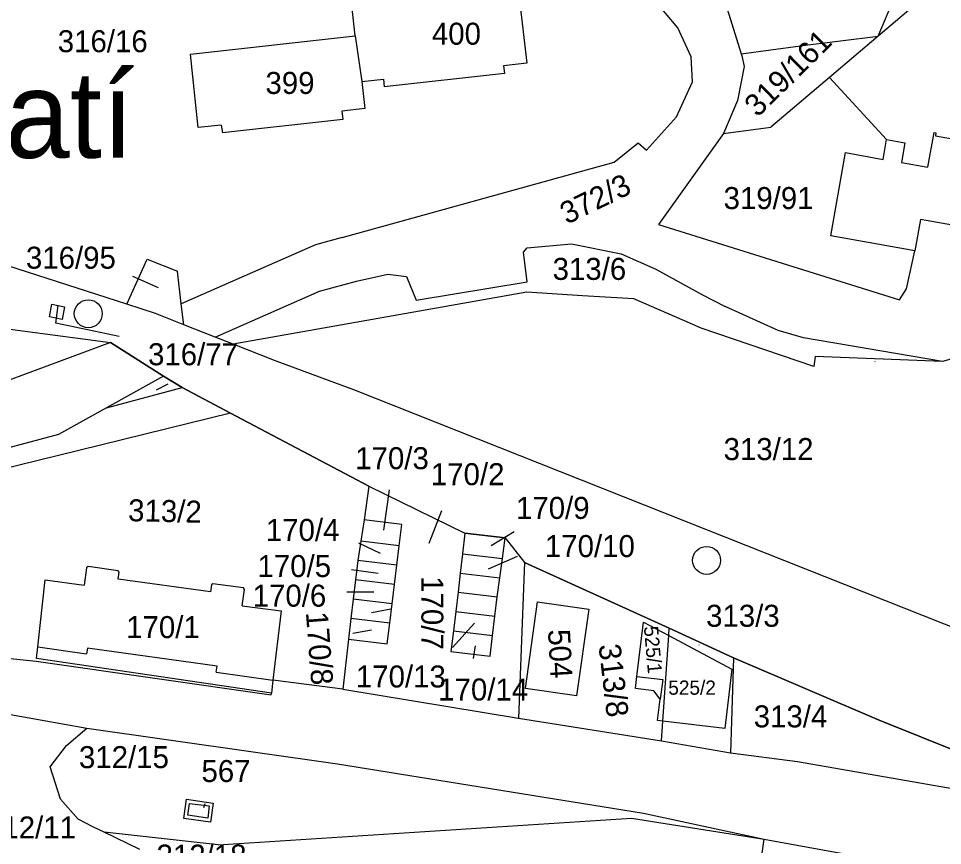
# Model space of a CAD drawing. Extents: x -805826 to -803822, y -1165880 to -1164382.
# Drawn here: x -805401.4 to -805258.6, y -1164970.8 to -1164843 of the extents above; entities that cross this region are included whole.
import ezdxf

# ---------------------------------------------------------------- set-up
doc = ezdxf.new("R2010")
doc.units = 0
for name, color, linetype in [('kilometráž - 2880', 7, 'Continuous'), ('kn_celek - Cisla parcel pomocna', 7, 'Continuous'), ('kn_celek - Cisla pozemkovych parcel', 7, 'Continuous'), ('kn_celek - Cisla stavebnich parcel', 7, 'Continuous'), ('kn_celek - Dalsi prvky mapy popis', 7, 'Continuous'), ('kn_celek - Hranice parcel', 7, 'Continuous'), ('kn_celek - Vnitrni kresby', 7, 'Continuous'), ('plochy - SZDC', 7, 'Continuous'), ('PSR_C2_3_celsit_Lenora - PS03', 7, 'Continuous')]:
    doc.layers.add(name, color=color, linetype=linetype)

msp = doc.modelspace()

# ---------------------------------------------------------------- linework, layer by layer
at = {"layer": 'kilometráž - 2880'}
for centre in [(-805390.66, -1164888.66), (-805295.08, -1164926.77)]:
    msp.add_circle(centre, 2.16, dxfattribs=at)
at = {"layer": 'kn_celek - Cisla parcel pomocna'}
for p, q in [((-805379.8, -1164884.67), (-805383.76, -1164882.91)), ((-805269.06, -1164896.09), (-805269.04, -1164896.05)), ((-805380.1, -1164900.43), (-805378.32, -1164899.51)), ((-805344.98, -1164922.09), (-805344.09, -1164915.85)), ((-805337.96, -1164924.11), (-805335.99, -1164919.04)), ((-805328.39, -1164924.47), (-805324.84, -1164922.32)), ((-805345.5, -1164925.73), (-805348.84, -1164924.12)), ((-805328.8, -1164928.05), (-805324.32, -1164926.14)), ((-805345.84, -1164928.82), (-805349.97, -1164928.23)), ((-805346.54, -1164931.66), (-805350.68, -1164931.68)), ((-805346.9, -1164934.83), (-805343.91, -1164934.27)), ((-805330.98, -1164936.47), (-805334.37, -1164940.23)), ((-805346.86, -1164937.55), (-805349.74, -1164938.06)), ((-805330.85, -1164939.97), (-805331.14, -1164941.94)), ((-805296.23, -1164939.86), (-805296.22, -1164939.83)), ((-805372.82, -1164964.95), (-805372.57, -1164964.33))]:
    msp.add_line(p, q, dxfattribs=at)
at = {"layer": 'kn_celek - Hranice parcel'}
for p, q in [((-805240.99, -1164822.34), (-805268.57, -1164845.77)), ((-805268.57, -1164845.77), (-805262.09, -1164830.37)), ((-805324.16, -1164838.62), (-805322.87, -1164849.93)), ((-805299.51, -1164844.46), (-805303.36, -1164839.88)), ((-805349.4, -1164845.7), (-805349.86, -1164841.51)), ((-805291.92, -1164841.55), (-805289.74, -1164848.48)), ((-805297.44, -1164848.94), (-805299.51, -1164844.46)), ((-805374.88, -1164848.55), (-805349.4, -1164845.7)), ((-805349.4, -1164845.7), (-805348.35, -1164852.77)), ((-805280.19, -1164847.23), (-805268.57, -1164845.77)), ((-805268.57, -1164845.77), (-805276.09, -1164852.16)), ((-805289.74, -1164848.48), (-805280.58, -1164847.28)), ((-805280.58, -1164847.28), (-805280.19, -1164847.23)), ((-805373.65, -1164859.9), (-805374.88, -1164848.55)), ((-805297.23, -1164852.85), (-805297.44, -1164848.94)), ((-805289.74, -1164848.48), (-805289.64, -1164848.81)), ((-805289.64, -1164848.81), (-805289.26, -1164850.48)), ((-805322.87, -1164849.93), (-805326.46, -1164850.33)), ((-805326.46, -1164850.33), (-805326.33, -1164851.53)), ((-805289.26, -1164850.48), (-805290.29, -1164855.73)), ((-805348.35, -1164852.77), (-805345.04, -1164852.41)), ((-805345.04, -1164852.41), (-805344.9, -1164853.61)), ((-805326.33, -1164851.53), (-805344.9, -1164853.61)), ((-805276.09, -1164852.16), (-805285.13, -1164859.84)), ((-805267.24, -1164861.75), (-805276.09, -1164852.16)), ((-805348.35, -1164852.77), (-805347.89, -1164856.97)), ((-805299.71, -1164858.21), (-805297.23, -1164852.85)), ((-805290.29, -1164855.73), (-805292.44, -1164860.82)), ((-805347.89, -1164856.97), (-805351.46, -1164857.37)), ((-805351.46, -1164857.37), (-805351.31, -1164858.63)), ((-805370.1, -1164859.5), (-805373.65, -1164859.9)), ((-805370.1, -1164859.5), (-805369.91, -1164860.72)), ((-805351.31, -1164858.63), (-805369.91, -1164860.72)), ((-805304.39, -1164863.37), (-805299.71, -1164858.21)), ((-805292.44, -1164860.82), (-805302.52, -1164874.87)), ((-805292.44, -1164860.82), (-805285.13, -1164859.84)), ((-805260.89, -1164866.03), (-805259.9, -1164860.66)), ((-805259.9, -1164860.66), (-805259.62, -1164860.71)), ((-805259.62, -1164860.71), (-805259.71, -1164861.19)), ((-805309.37, -1164865.23), (-805305.67, -1164862.23)), ((-805305.67, -1164862.23), (-805304.39, -1164863.37)), ((-805267.78, -1164864.81), (-805267.24, -1164861.75)), ((-805267.24, -1164861.75), (-805264.43, -1164862.24)), ((-805264.43, -1164862.24), (-805264.96, -1164865.31)), ((-805259.71, -1164861.19), (-805241.37, -1164864.44)), ((-805275.89, -1164876.63), (-805273.59, -1164863.77)), ((-805273.59, -1164863.77), (-805267.78, -1164864.81)), ((-805351.41, -1164876.9), (-805309.37, -1164865.23)), ((-805264.96, -1164865.31), (-805260.89, -1164866.03)), ((-805302.52, -1164874.87), (-805265.25, -1164886.52)), ((-805262, -1164874.09), (-805262.86, -1164878.93)), ((-805243.35, -1164877.38), (-805262, -1164874.09)), ((-805262.86, -1164878.93), (-805275.89, -1164876.63)), ((-805384.69, -1164887.2), (-805415.73, -1164877.21)), ((-805355.51, -1164878.02), (-805376.28, -1164887.14)), ((-805351.41, -1164876.9), (-805355.51, -1164878.02)), ((-805322.79, -1164878.48), (-805315.96, -1164877.88)), ((-805315.96, -1164877.88), (-805308.27, -1164879.4)), ((-805323.39, -1164879.15), (-805322.79, -1164878.48)), ((-805322.83, -1164883.71), (-805323.39, -1164879.15)), ((-805308.27, -1164879.4), (-805302.92, -1164881.78)), ((-805264.17, -1164884.81), (-805262.86, -1164878.93)), ((-805384.69, -1164887.2), (-805381.56, -1164880.22)), ((-805381.56, -1164880.22), (-805376.86, -1164882.1)), ((-805376.28, -1164887.14), (-805376.86, -1164882.1)), ((-805302.92, -1164881.78), (-805295.73, -1164885.73)), ((-805354.91, -1164885.18), (-805349.21, -1164883.62)), ((-805349.21, -1164883.62), (-805344.37, -1164882.54)), ((-805344.37, -1164882.54), (-805341.49, -1164882.89)), ((-805341.49, -1164882.89), (-805339.98, -1164886.56)), ((-805339.98, -1164886.56), (-805322.83, -1164883.71)), ((-805371.02, -1164892.27), (-805354.91, -1164885.18)), ((-805265.25, -1164886.52), (-805264.17, -1164884.81)), ((-805322.87, -1164885.33), (-805368.25, -1164893.36)), ((-805314.24, -1164885.88), (-805322.87, -1164885.33)), ((-805306.3, -1164886.38), (-805314.24, -1164885.88)), ((-805298.48, -1164889.78), (-805306.3, -1164886.38)), ((-805295.73, -1164885.73), (-805292.23, -1164887.55)), ((-805380.25, -1164888.64), (-805384.69, -1164887.2)), ((-805375.9, -1164890.35), (-805376.28, -1164887.14)), ((-805284.01, -1164891.23), (-805292.23, -1164887.55)), ((-805419.07, -1164888.85), (-805387.24, -1164893.09)), ((-805375.9, -1164890.35), (-805380.25, -1164888.64)), ((-805371.02, -1164892.27), (-805375.9, -1164890.35)), ((-805295.93, -1164890.89), (-805298.48, -1164889.78)), ((-805278.52, -1164896.83), (-805295.93, -1164890.89)), ((-805368.25, -1164893.36), (-805371.02, -1164892.27)), ((-805280.12, -1164892.37), (-805284.01, -1164891.23)), ((-805258.61, -1164896.04), (-805280.12, -1164892.37)), ((-805387.24, -1164893.09), (-805416.15, -1164903.86)), ((-805379.01, -1164898.31), (-805387.24, -1164893.09)), ((-805361.85, -1164895.88), (-805368.25, -1164893.36)), ((-805252.02, -1164894.15), (-805258.61, -1164896.04)), ((-805354.52, -1164898.6), (-805361.85, -1164895.88)), ((-805278.27, -1164895.27), (-805278.52, -1164896.83)), ((-805258.61, -1164896.04), (-805278.27, -1164895.27)), ((-805379.01, -1164898.31), (-805387.82, -1164903.18)), ((-805376.17, -1164900.07), (-805379.01, -1164898.31)), ((-805349.61, -1164900.43), (-805354.52, -1164898.6)), ((-805387.82, -1164903.18), (-805376.17, -1164900.07)), ((-805368.7, -1164904.02), (-805376.17, -1164900.07)), ((-805295.17, -1164922), (-805349.61, -1164900.43)), ((-805387.82, -1164903.18), (-805395.26, -1164907.31)), ((-805368.7, -1164904.02), (-805395.24, -1164910.56)), ((-805347.29, -1164915.29), (-805368.7, -1164904.02)), ((-805395.26, -1164907.31), (-805414.79, -1164912.55)), ((-805395.24, -1164910.56), (-805436.32, -1164920.55)), ((-805347.29, -1164915.29), (-805348.01, -1164920.48)), ((-805347.29, -1164915.29), (-805332.43, -1164922.56)), ((-805348.01, -1164920.48), (-805348.52, -1164923.81)), ((-805342.18, -1164921.22), (-805348.01, -1164920.48)), ((-805342.58, -1164924.53), (-805342.18, -1164921.22)), ((-805250.01, -1164939.9), (-805295.17, -1164922)), ((-805348.52, -1164923.81), (-805348.97, -1164926.8)), ((-805342.58, -1164924.53), (-805348.52, -1164923.81)), ((-805332.43, -1164922.56), (-805332.8, -1164925.77)), ((-805326.19, -1164923.31), (-805332.43, -1164922.56)), ((-805326.63, -1164926.5), (-805326.19, -1164923.31)), ((-805326.19, -1164923.31), (-805323.2, -1164927.11)), ((-805342.95, -1164927.53), (-805342.58, -1164924.53)), ((-805332.8, -1164925.77), (-805333.15, -1164928.72)), ((-805332.8, -1164925.77), (-805326.63, -1164926.5)), ((-805327.04, -1164929.45), (-805326.63, -1164926.5)), ((-805390.93, -1164927.91), (-805391.3, -1164930.6)), ((-805390.7, -1164927.74), (-805390.93, -1164927.91)), ((-805386.05, -1164928.39), (-805390.7, -1164927.74)), ((-805348.97, -1164926.8), (-805349.33, -1164929.78)), ((-805342.95, -1164927.53), (-805348.97, -1164926.8)), ((-805343.31, -1164930.52), (-805342.95, -1164927.53)), ((-805323.2, -1164927.11), (-805324.17, -1164951.15)), ((-805300.85, -1164937.24), (-805323.2, -1164927.11)), ((-805385.88, -1164928.61), (-805386.05, -1164928.39)), ((-805386.03, -1164929.67), (-805385.88, -1164928.61)), ((-805333.15, -1164928.72), (-805333.5, -1164931.7)), ((-805333.15, -1164928.72), (-805327.04, -1164929.45)), ((-805327.44, -1164932.42), (-805327.04, -1164929.45)), ((-805398.46, -1164940.13), (-805397.34, -1164929.8)), ((-805397.34, -1164929.8), (-805391.3, -1164930.6)), ((-805371.78, -1164931.61), (-805386.03, -1164929.67)), ((-805371.62, -1164930.55), (-805371.78, -1164931.61)), ((-805371.4, -1164930.38), (-805371.62, -1164930.55)), ((-805366.68, -1164931.03), (-805371.4, -1164930.38)), ((-805349.33, -1164929.78), (-805349.7, -1164932.76)), ((-805343.31, -1164930.52), (-805349.33, -1164929.78)), ((-805343.68, -1164933.49), (-805343.31, -1164930.52)), ((-805366.87, -1164933.8), (-805366.51, -1164931.26)), ((-805366.51, -1164931.26), (-805366.68, -1164931.03)), ((-805333.5, -1164931.7), (-805333.86, -1164934.68)), ((-805333.5, -1164931.7), (-805327.44, -1164932.42)), ((-805366.87, -1164933.8), (-805360.86, -1164934.59)), ((-805349.7, -1164932.76), (-805350.06, -1164935.74)), ((-805343.68, -1164933.49), (-805349.7, -1164932.76)), ((-805344.04, -1164936.48), (-805343.68, -1164933.49)), ((-805327.8, -1164935.39), (-805327.44, -1164932.42)), ((-805323.06, -1164946.57), (-805321.21, -1164933.16)), ((-805321.21, -1164933.16), (-805313.27, -1164934.3)), ((-805360.86, -1164934.59), (-805362.11, -1164945.26)), ((-805333.86, -1164934.68), (-805334.21, -1164937.66)), ((-805333.86, -1164934.68), (-805327.8, -1164935.39)), ((-805313.27, -1164934.3), (-805315.18, -1164947.69)), ((-805350.06, -1164935.74), (-805350.45, -1164938.94)), ((-805344.04, -1164936.48), (-805350.06, -1164935.74)), ((-805344.43, -1164939.67), (-805344.04, -1164936.48)), ((-805328.15, -1164938.37), (-805327.8, -1164935.39)), ((-805305.86, -1164944.71), (-805304.83, -1164936.3)), ((-805304.83, -1164936.3), (-805300.93, -1164938.38)), ((-805334.21, -1164937.66), (-805334.59, -1164940.85)), ((-805334.21, -1164937.66), (-805328.15, -1164938.37)), ((-805300.93, -1164938.38), (-805300.85, -1164937.24)), ((-805290.94, -1164941.81), (-805300.85, -1164937.24)), ((-805350.45, -1164938.94), (-805351.29, -1164946.69)), ((-805350.45, -1164938.94), (-805344.43, -1164939.67)), ((-805328.54, -1164941.57), (-805328.15, -1164938.37)), ((-805301.84, -1164951.63), (-805300.93, -1164938.38)), ((-805300.93, -1164938.38), (-805291.18, -1164943.57)), ((-805398.65, -1164941.91), (-805398.46, -1164940.13)), ((-805334.59, -1164940.85), (-805328.54, -1164941.57)), ((-805404.99, -1164941.68), (-805398.7, -1164942.36)), ((-805398.7, -1164942.36), (-805362.37, -1164947.56)), ((-805362.33, -1164947.27), (-805398.65, -1164941.91)), ((-805290.94, -1164941.81), (-805291.37, -1164956.53)), ((-805268.41, -1164951.46), (-805290.94, -1164941.81)), ((-805291.18, -1164943.57), (-805292.27, -1164952.74)), ((-805362.11, -1164945.26), (-805362.33, -1164947.27)), ((-805351.29, -1164946.69), (-805362.11, -1164945.26)), ((-805306.09, -1164946.58), (-805305.86, -1164944.71)), ((-805351.29, -1164946.69), (-805324.17, -1164951.15)), ((-805315.18, -1164947.69), (-805323.06, -1164946.57)), ((-805303.21, -1164946.95), (-805306.09, -1164946.58)), ((-805362.37, -1164947.56), (-805362.33, -1164947.27)), ((-805302.26, -1164948.2), (-805303.21, -1164946.95)), ((-805302.64, -1164951.53), (-805302.26, -1164948.2)), ((-805406.54, -1164949.88), (-805390.87, -1164952.7)), ((-805324.17, -1164951.15), (-805302.05, -1164954.63)), ((-805301.84, -1164951.63), (-805302.64, -1164951.53)), ((-805302.05, -1164954.63), (-805301.84, -1164951.63)), ((-805292.27, -1164952.74), (-805301.84, -1164951.63)), ((-805235.68, -1164964.57), (-805268.41, -1164951.46)), ((-805394.05, -1164955.35), (-805390.87, -1164952.7)), ((-805390.87, -1164952.7), (-805352.14, -1164958.23)), ((-805302.05, -1164954.63), (-805291.37, -1164956.53)), ((-805396.55, -1164958.65), (-805394.05, -1164955.35)), ((-805291.37, -1164956.53), (-805281.04, -1164957.84)), ((-805281.04, -1164957.84), (-805235.82, -1164965.77)), ((-805394.96, -1164963.64), (-805396.55, -1164958.65)), ((-805352.14, -1164958.23), (-805304.83, -1164965.82)), ((-805392.24, -1164966.77), (-805394.96, -1164963.64)), ((-805375.89, -1164966.64), (-805375.49, -1164963.69)), ((-805375.49, -1164963.69), (-805371.36, -1164964.28)), ((-805371.36, -1164964.28), (-805371.76, -1164967.2)), ((-805371.76, -1164967.2), (-805375.89, -1164966.64)), ((-805370.56, -1164970.71), (-805306.66, -1164966.6)), ((-805306.66, -1164966.6), (-805286.2, -1164969.87)), ((-805304.83, -1164965.82), (-805286.2, -1164969.87)), ((-805389.84, -1164967.97), (-805392.24, -1164966.77)), ((-805388.22, -1164968.76), (-805389.84, -1164967.97)), ((-805370.56, -1164970.71), (-805388.22, -1164968.76)), ((-805382.7, -1164971.43), (-805388.22, -1164968.76)), ((-805287.19, -1164976.81), (-805286.2, -1164969.87)), ((-805286.2, -1164969.87), (-805233.69, -1164979.3))]:
    msp.add_line(p, q, dxfattribs=at)
at = {"layer": 'kn_celek - Vnitrni kresby'}
for p, q in [((-805398.46, -1164940.13), (-805390.92, -1164941.2)), ((-805390.79, -1164940.31), (-805390.92, -1164941.2)), ((-805370.75, -1164943.13), (-805390.79, -1164940.31)), ((-805370.88, -1164944.02), (-805370.75, -1164943.13)), ((-805370.88, -1164944.02), (-805362.11, -1164945.26)), ((-805305.86, -1164944.71), (-805301.86, -1164945.16)), ((-805301.86, -1164945.16), (-805302.26, -1164948.2)), ((-805375.29, -1164966.16), (-805375.02, -1164964.31)), ((-805375.02, -1164964.31), (-805371.97, -1164964.72)), ((-805371.97, -1164964.72), (-805372.2, -1164966.58)), ((-805372.2, -1164966.58), (-805375.29, -1164966.16))]:
    msp.add_line(p, q, dxfattribs=at)
at = {"layer": 'plochy - SZDC'}
for p, q in [((-805384.69, -1164887.2), (-805415.73, -1164877.21)), ((-805380.25, -1164888.64), (-805384.69, -1164887.2)), ((-805419.07, -1164888.85), (-805387.24, -1164893.09)), ((-805375.9, -1164890.35), (-805380.25, -1164888.64)), ((-805371.02, -1164892.27), (-805375.9, -1164890.35)), ((-805368.25, -1164893.36), (-805371.02, -1164892.27)), ((-805387.24, -1164893.09), (-805379.01, -1164898.31)), ((-805361.85, -1164895.88), (-805368.25, -1164893.36)), ((-805354.52, -1164898.6), (-805361.85, -1164895.88)), ((-805379.01, -1164898.31), (-805376.17, -1164900.07)), ((-805349.61, -1164900.43), (-805354.52, -1164898.6)), ((-805376.17, -1164900.07), (-805368.7, -1164904.02)), ((-805295.17, -1164922), (-805349.61, -1164900.43)), ((-805368.7, -1164904.02), (-805347.29, -1164915.29)), ((-805347.29, -1164915.29), (-805332.43, -1164922.56)), ((-805250.01, -1164939.9), (-805295.17, -1164922)), ((-805332.43, -1164922.56), (-805326.19, -1164923.31)), ((-805326.19, -1164923.31), (-805323.2, -1164927.11)), ((-805323.2, -1164927.11), (-805300.85, -1164937.24)), ((-805300.85, -1164937.24), (-805290.94, -1164941.81)), ((-805290.94, -1164941.81), (-805268.41, -1164951.46)), ((-805268.41, -1164951.46), (-805235.68, -1164964.57))]:
    msp.add_line(p, q, dxfattribs=at)
at = {"layer": 'PSR_C2_3_celsit_Lenora - PS03'}
msp.add_lwpolyline([(-805396.29, -1164887.2), (-805394.33, -1164887.58), (-805394.71, -1164889.54), (-805396.67, -1164889.16)], close=True, dxfattribs=at)
msp.add_lwpolyline([(-805385.91, -1164892.2), (-805395.7, -1164890.12), (-805395.31, -1164887.39)], dxfattribs=at)

# ---------------------------------------------------------------- texts
at = {"layer": 'kn_celek - Cisla parcel pomocna'}
for s, p in [('316/95', (-805400.3, -1164881.7)), ('316/77', (-805381.42, -1164896.62)), ('170/3', (-805349.39, -1164912.68)), ('170/2', (-805337.7, -1164915.15)), ('170/9', (-805324.54, -1164920.36)), ('170/4', (-805363.21, -1164923.77)), ('170/10', (-805320.07, -1164926.26)), ('170/5', (-805364.5, -1164929.35)), ('170/6', (-805365.25, -1164933.92)), ('313/3', (-805295.15, -1164937.03)), ('170/13', (-805349.29, -1164946.41)), ('170/14', (-805336.56, -1164948.42)), ('567', (-805373.16, -1164961.02))]:
    msp.add_text(s, height=3.4, dxfattribs=at).set_placement(p)
for s, rotation, p in [('170/7', 269.982, (-805339.17, -1164929.21)), ('170/8', 274.392, (-805357.03, -1164934.8))]:
    msp.add_text(s, height=3.4, rotation=rotation, dxfattribs=at).set_placement(p)
at = {"layer": 'kn_celek - Cisla pozemkovych parcel'}
for s, height, p in [('316/16', 3.4, (-805395.38, -1164848.25)), ('319/91', 3.4, (-805292.45, -1164872.49)), ('313/6', 3.4, (-805318.88, -1164883.43)), ('316/95', 0.005, (-805379.8, -1164884.67)), ('316/77', 0.005, (-805380.1, -1164900.43)), ('313/12', 3.4, (-805292.45, -1164911.27)), ('313/3', 0.005, (-805296.23, -1164939.86)), ('313/4', 3.4, (-805287.79, -1164952.57)), ('312/15', 3.4, (-805392.1, -1164958.87)), ('312/11', 3.4, (-805406.47, -1164969.74)), ('312/18', 3.4, (-805380.1, -1164974.09))]:
    msp.add_text(s, height=height, dxfattribs=at).set_placement(p)
for s, rotation, p in [('319/161', 44.46, (-805287.19, -1164858.41)), ('372/3', 25.956, (-805316.67, -1164874.92)), ('313/2', 358.731, (-805384.53, -1164920.71)), ('313/8', 276.57, (-805311.78, -1164939.85))]:
    msp.add_text(s, height=3.4, rotation=rotation, dxfattribs=at).set_placement(p)
at = {"layer": 'kn_celek - Cisla stavebnich parcel'}
for s, height, p in [('400', 3.4, (-805337.54, -1164847.09)), ('399', 3.4, (-805363.27, -1164854.7)), ('170/3', 0.005, (-805344.98, -1164922.09)), ('170/2', 0.005, (-805337.96, -1164924.11)), ('170/9', 0.005, (-805328.39, -1164924.47)), ('170/4', 0.005, (-805345.5, -1164925.73)), ('170/10', 0.005, (-805328.8, -1164928.05)), ('170/5', 0.005, (-805345.84, -1164928.82)), ('170/11', 0.005, (-805330.31, -1164930.8)), ('170/6', 0.005, (-805346.54, -1164931.66)), ('170/12', 0.005, (-805330.56, -1164933.55)), ('170/1', 3.4, (-805384.8, -1164938.78)), ('170/7', 0.005, (-805346.9, -1164934.83)), ('170/13', 0.005, (-805330.98, -1164936.47)), ('170/8', 0.005, (-805346.86, -1164937.55)), ('170/14', 0.005, (-805330.85, -1164939.97)), ('525/2', 2.2, (-805301, -1164947.53)), ('567', 0.005, (-805372.82, -1164964.95))]:
    msp.add_text(s, height=height, dxfattribs=at).set_placement(p)
for s, height, rotation, p in [('504', 3.4, 273.069, (-805319.6, -1164937.5)), ('525/1', 2.2, 275.076, (-805304.78, -1164937.02))]:
    msp.add_text(s, height=height, rotation=rotation, dxfattribs=at).set_placement(p)
at = {"layer": 'kn_celek - Dalsi prvky mapy popis'}
msp.add_text('Nad tratí', height=13.4, dxfattribs=at).set_placement((-805452.28, -1164864.57))

doc.saveas('drawing.dxf')
